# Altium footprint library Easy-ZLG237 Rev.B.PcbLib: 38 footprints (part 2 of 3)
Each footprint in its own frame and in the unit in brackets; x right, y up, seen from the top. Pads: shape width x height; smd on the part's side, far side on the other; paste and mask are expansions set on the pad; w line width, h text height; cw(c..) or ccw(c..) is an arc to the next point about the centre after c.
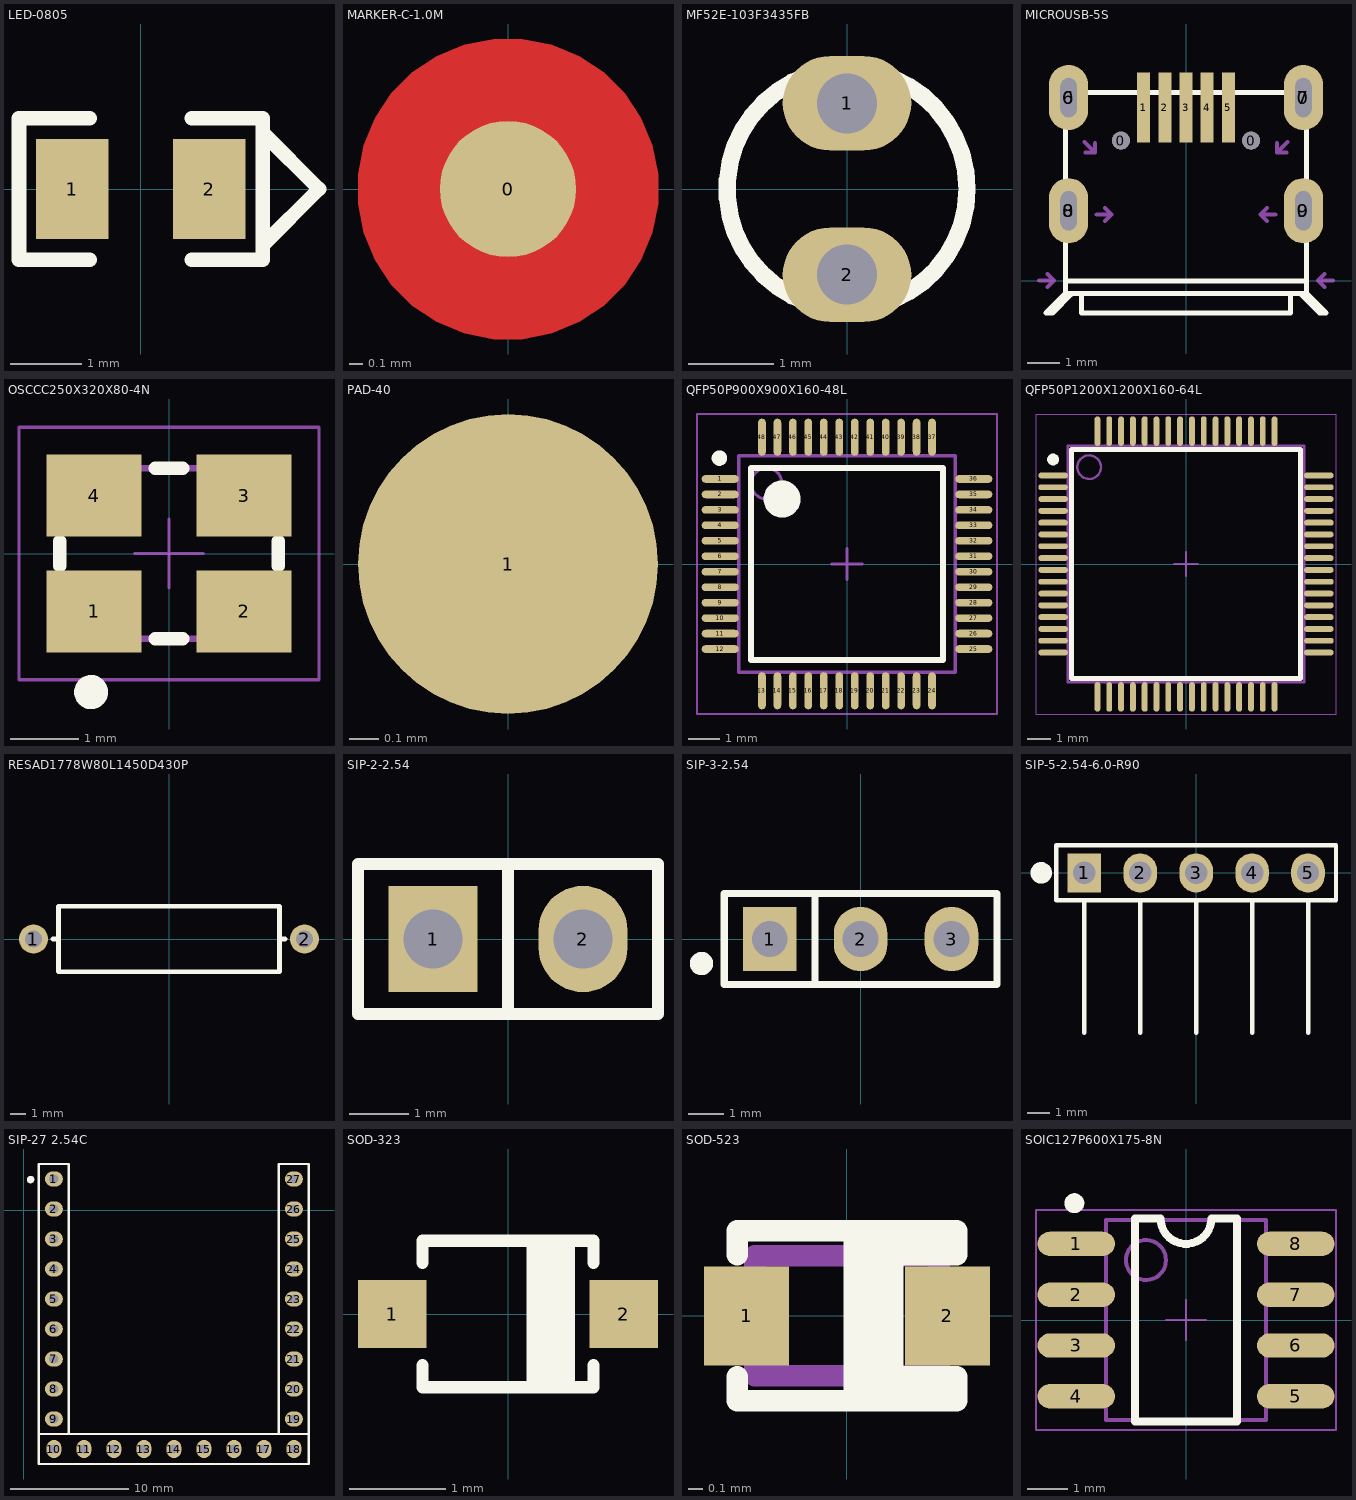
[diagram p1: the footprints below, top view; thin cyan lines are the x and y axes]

## LED-0805 [mm] "170907内距改0.9mm"
pads (2):
  rect 1.014x1.4 smd: 1(-0.957,0) 2(0.957,0)
Top Overlay:
  lines w0.203: -0.711,-0.991 -1.702,-0.991 -1.702,0.991 -0.711,0.991 ; 0.711,-0.991 1.702,-0.991 1.702,0.991 0.711,0.991 ; 1.702,-0.787 2.489,0 1.702,0.787
3D body: height 0.64, standoff 0, extent -1,-0.635 1,0.635
3D body: height 1.1, standoff 0, extent -0.508,-0.508 0.508,0.508

## MARKER-C-1.0M [mm]
height 18.4
pads (1):
  round 1 smd paste-1.016 mask+0.5: 0(0,0)
Top Layer:
  pour cut-out: -1.1,0 -1.1,-0.108 -1.058,-0.321 -0.975,-0.521 -0.854,-0.701 -0.701,-0.854 -0.521,-0.975 -0.321,-1.058 -0.108,-1.1 0,-1.1 0.108,-1.1 0.321,-1.058 0.521,-0.975 0.701,-0.854 0.854,-0.701 0.975,-0.521 1.058,-0.321 1.1,-0.108 1.1,0 1.1,0.108 1.058,0.321 0.975,0.521 0.854,0.701 0.701,0.854 0.521,0.975 0.321,1.058 0.108,1.1 0,1.1 -0.108,1.1 -0.321,1.058 -0.521,0.975 -0.701,0.854 -0.854,0.701 -0.975,0.521 -1.058,0.321 -1.1,0.108

## MF52E-103F3435FB [mm]
pads (2):
  oval 1.5x1.1 hole 0.7: 1(0,1) 2(0,-1)
Top Overlay:
  circle w0.2: c0,0 r1.4

## MICROUSB-5S [mm]
height 0.2
pads (15):
  oval 1.2x2 on Top Paste: 0(-3.6,2.15) 0(-3.6,5.62) 0(3.6,2.15) 0(3.6,5.62)
  round 0.54 hole 0.55 unplated: 0(-2,4.3) 0(2,4.3)
  rect 0.4x2.15 smd: 1(-1.3,5.31) 2(-0.65,5.31) 3(0,5.31) 4(0.65,5.31) 5(1.3,5.31)
  oval 1.2x2 hole 0.5 slot 1.2 at 90 deg: 6(-3.6,5.62) 7(3.6,5.62) 8(-3.6,2.15) 9(3.6,2.15)
Top Overlay:
  lines w0.152: -3.7,0 3.7,0 ; -3.7,0.012 -3.7,5.77 3.7,5.77 3.7,0.012 ; -3.7,0.062 -3.7,-0.388 ; -3.5,-0.398 -4.09,-0.988 -4.3,-0.988 -3.7,-0.388 ; -3.2,-0.388 -3.2,-0.988 3.2,-0.988 3.2,-0.388 ; 3.5,-0.388 4.1,-0.988 4.3,-0.988 3.7,-0.388 ; 3.7,0.062 3.7,-0.388 ; -3.7,-0.388 3.7,-0.388
Mechanical 15:
  lines w0.127: -4.5,0.012 -4.05,0.012 ; -4.25,-0.188 -4.05,0.012 ; -4.25,0.212 -4.05,0.012 ; -3.112,4.255 -2.794,3.937 ; -3.077,3.937 -2.794,3.937 ; -2.794,4.22 -2.794,3.937 ; -2.736,2.032 -2.286,2.032 ; -2.486,1.832 -2.286,2.032 ; -2.486,2.232 -2.286,2.032 ; 2.486,1.832 2.286,2.032 ; 2.486,2.232 2.286,2.032 ; 2.736,2.032 2.286,2.032 ; 2.794,4.22 2.794,3.937 ; 3.077,3.937 2.794,3.937 ; 3.112,4.255 2.794,3.937 ; 4.25,-0.188 4.05,0.012 ; 4.25,0.212 4.05,0.012 ; 4.5,0.012 4.05,0.012
  text "PCB EDGE" at -3,0.212 h0.91
  text "TopPaste" at -2.794,2.667 h0.91

## OSCCC250X320X80-4N [mm]
height 0.8
pads (4):
  rect 1.4x1.2 smd: 1(-1.1,-0.85) 2(1.1,-0.85) 3(1.1,0.85) 4(-1.1,0.85)
Top Overlay:
  circle w0.25: c-1.143,-2.032 r0.125
  lines w0.2: -1.6,-0.178 -1.6,0.178 ; -0.203,-1.25 0.203,-1.25 ; -0.203,1.25 0.203,1.25 ; 1.6,-0.178 1.6,0.178
Mechanical 13:
  lines w0.1: -1.6,-1.15 -1.5,-1.25 ; -1.6,-1.05 -1.4,-1.25 ; -1.6,-0.95 -1.3,-1.25 ; -1.6,-0.85 -1.2,-1.25 ; -1.6,-0.75 -1.1,-1.25 ; -1.6,-0.65 -1,-1.25 ; -1.6,-0.55 -0.9,-1.25 ; -1.6,-0.45 -0.8,-1.25 ; -1.6,-0.35 -0.7,-1.25 ; -1.6,-0.25 -0.6,-1.25 ; -1.6,-1.25 -1.6,1.25 1.6,1.25 1.6,-1.25 -1.6,-1.25
Mechanical 15:
  lines w0.05: -0.5,0 0.5,0 ; 0,-0.5 0,0.5 ; -2.2,-1.85 -2.2,1.85 2.2,1.85 2.2,-1.85 -2.2,-1.85

## PAD-40 [mil]
pads (1):
  round 40 smd paste-43.31: 1(0,0)

## QFP50P900X900X160-48L [mm] "QFP, 48-Leads, Body 7.00x7.00mm, Pitch 0.50mm, IPC High Density"
height 1.6
pads (48):
  oval 1.2x0.25 smd mask+0.051: 1(-4.1,2.75) 2(-4.1,2.25) 3(-4.1,1.75) 4(-4.1,1.25) 5(-4.1,0.75) 6(-4.1,0.25) 7(-4.1,-0.25) 8(-4.1,-0.75) 9(-4.1,-1.25) 10(-4.1,-1.75) 11(-4.1,-2.25) 12(-4.1,-2.75) 25(4.1,-2.75) 26(4.1,-2.25) 27(4.1,-1.75) 28(4.1,-1.25) 29(4.1,-0.75) 30(4.1,-0.25) 31(4.1,0.25) 32(4.1,0.75) 33(4.1,1.25) 34(4.1,1.75) 35(4.1,2.25) 36(4.1,2.75)
  oval 0.25x1.2 smd mask+0.051: 13(-2.75,-4.1) 14(-2.25,-4.1) 15(-1.75,-4.1) 16(-1.25,-4.1) 17(-0.75,-4.1) 18(-0.25,-4.1) 19(0.25,-4.1) 20(0.75,-4.1) 21(1.25,-4.1) 22(1.75,-4.1) 23(2.25,-4.1) 24(2.75,-4.1) 37(2.75,4.1) 38(2.25,4.1) 39(1.75,4.1) 40(1.25,4.1) 41(0.75,4.1) 42(0.25,4.1) 43(-0.25,4.1) 44(-0.75,4.1) 45(-1.25,4.1) 46(-1.75,4.1) 47(-2.25,4.1) 48(-2.75,4.1)
Top Overlay:
  circle w0.6: c-2.1,2.1 r0.3
  circle w0.25: c-4.125,3.425 r0.125
  lines w0.2: -3.1,-3.1 3.1,-3.1 3.1,3.1 -3.1,3.1 -3.1,-3.1
Mechanical 13:
  circle w0.1: c-2.6,2.6 r0.5
  lines w0.1: -3.5,-3.5 3.5,-3.5 3.5,3.5 -3.5,3.5 -3.5,-3.5
Mechanical 15:
  lines w0.05: -4.85,-4.85 4.85,-4.85 4.85,4.85 -4.85,4.85 -4.85,-4.85
  lines w0.1: -0.5,0 0.5,0 ; 0,-0.5 0,0.5
3D body: height 1.6, standoff 0.05, extent -3.5,-3.5 3.5,3.5

## QFP50P1200X1200X160-64L [mm] "QFP, 64-Leads, Body 10.00x10.00mm, Pitch 0.50mm, IPC High Density"
height 1.6
pads (64):
  oval 1.25x0.25 smd mask+0.051: 1(-5.625,3.75) 2(-5.625,3.25) 3(-5.625,2.75) 4(-5.625,2.25) 5(-5.625,1.75) 6(-5.625,1.25) 7(-5.625,0.75) 8(-5.625,0.25) 9(-5.625,-0.25) 10(-5.625,-0.75) 11(-5.625,-1.25) 12(-5.625,-1.75) 13(-5.625,-2.25) 14(-5.625,-2.75) 15(-5.625,-3.25) 16(-5.625,-3.75) 33(5.625,-3.75) 34(5.625,-3.25) 35(5.625,-2.75) 36(5.625,-2.25) 37(5.625,-1.75) 38(5.625,-1.25) 39(5.625,-0.75) 40(5.625,-0.25) 41(5.625,0.25) 42(5.625,0.75) 43(5.625,1.25) 44(5.625,1.75) 45(5.625,2.25) 46(5.625,2.75) 47(5.625,3.25) 48(5.625,3.75)
  oval 0.25x1.25 smd mask+0.051: 17(-3.75,-5.625) 18(-3.25,-5.625) 19(-2.75,-5.625) 20(-2.25,-5.625) 21(-1.75,-5.625) 22(-1.25,-5.625) 23(-0.75,-5.625) 24(-0.25,-5.625) 25(0.25,-5.625) 26(0.75,-5.625) 27(1.25,-5.625) 28(1.75,-5.625) 29(2.25,-5.625) 30(2.75,-5.625) 31(3.25,-5.625) 32(3.75,-5.625) 49(3.75,5.625) 50(3.25,5.625) 51(2.75,5.625) 52(2.25,5.625) 53(1.75,5.625) 54(1.25,5.625) 55(0.75,5.625) 56(0.25,5.625) 57(-0.25,5.625) 58(-0.75,5.625) 59(-1.25,5.625) 60(-1.75,5.625) 61(-2.25,5.625) 62(-2.75,5.625) 63(-3.25,5.625) 64(-3.75,5.625)
Top Overlay:
  circle w0.25: c-5.625,4.425 r0.125
  lines w0.2: -4.85,-4.85 4.85,-4.85 4.85,4.85 -4.85,4.85 -4.85,-4.85
Mechanical 13:
  circle w0.1: c-4.1,4.1 r0.5
  lines w0.1: -5,-5 5,-5 5,5 -5,5 -5,-5
Mechanical 15:
  lines w0.05: -6.35,-6.35 6.35,-6.35 6.35,6.35 -6.35,6.35 -6.35,-6.35
  lines w0.1: -0.5,0 0.5,0 ; 0,-0.5 0,0.5
3D body: height 1.6, standoff 0.05, extent -5,-5 5,5

## RESAD1778W80L1450D430P [mm]
height 1.905
pads (2):
  round 1.9 hole 1.1: 1(-8.89,0) 2(8.89,0)
Top Overlay:
  lines w0.305: -7.62,0 -7.239,0 ; 7.239,0 7.62,0 ; -7.25,-2.15 -7.25,2.15 7.25,2.15 7.25,-2.15 -7.25,-2.15

## SIP-2-2.54 [mm]
pads (2):
  rect 1.5x1.8 hole 1: 1(-1.27,0)
  oval 1.5x1.8 hole 1: 2(1.27,0)
Top Overlay:
  lines w0.2: 0,-1.27 0,1.27 ; -2.54,-1.27 -2.54,1.27 2.54,1.27 2.54,-1.27 -2.54,-1.27
3D body "HEADER.STEP": height 7.58, standoff -2.94, extent -2.54,-1.27 0,1.27
3D body "HEADER.STEP": height 7.58, standoff -2.94, extent 0,-1.27 2.54,1.27

## SIP-3-2.54 [mm]
pads (3):
  rect 1.5x1.8 hole 1: 1(-2.54,0)
  oval 1.5x1.8 hole 1: 2(0,0) 3(2.54,0)
Top Overlay:
  circle w0.4: c-4.445,-0.686 r0.125
  lines w0.2: -1.27,-1.27 -1.27,1.27 ; -3.81,-1.27 -3.81,1.27 3.81,1.27 3.81,-1.27 -3.81,-1.27
3D body "HEADER.STEP": height 7.58, standoff -2.94, extent -3.81,-1.27 -1.27,1.27
3D body "HEADER.STEP": height 7.58, standoff -2.94, extent -1.27,-1.27 1.27,1.27
3D body "HEADER.STEP": height 7.58, standoff -2.94, extent 1.27,-1.27 3.81,1.27

## SIP-5-2.54-6.0-R90 [mil] "引脚伸出部分为6.0mm"
pads (5):
  rect 60x70 hole 40: 1(-200,0)
  oval 60x70 hole 40: 2(-100,0) 3(0,0) 4(100,0) 5(200,0)
Top Overlay:
  circle w20: c-277,0.22 r9.22
  lines w8: -200,-285.43 -200,-49.21 ; -100,-285.43 -100,-49.21 ; 0,-285.43 0,-49.21 ; 100,-285.43 100,-49.21 ; 200,-285.43 200,-49.21 ; -250,-49.21 250,-49.21 250,49.21 -250,49.21 -250,-49.21

## SIP-27 2.54C [mil]
pads (27):
  oval 60x50 hole 31.5: 1(100,105) 2(100,5) 3(100,-95) 4(100,-195) 5(100,-295) 6(100,-395) 7(100,-495) 8(100,-595) 9(100,-695) 19(900,-695) 20(900,-595) 21(900,-495) 22(900,-395) 23(900,-295) 24(900,-195) 25(900,-95) 26(900,5) 27(900,105)
  oval 50x60 hole 31.5: 10(100,-795) 11(200,-795) 12(300,-795) 13(400,-795) 14(500,-795) 15(600,-795) 16(700,-795) 17(800,-795) 18(900,-795)
Top Overlay:
  circle w15: c22.01,103 r5
  lines w8: 945,-845 50,-845 50,-745 ; 945,-745 50,-745 ; 950,-845 950,-745 ; 50,-745 50,155 150,155 150,-745 50,-745 ; 950,-745 850,-745 850,155 950,155 950,-745

## SOD-323 [mil]
height 38
pads (2):
  rect 28x28 smd: 1(-47.5,0) 2(47.5,0)
Top Overlay:
  lines w5: -35,-21 -35,-30 35,-30 35,-21 ; -35,21 -35,30 35,30 35,21 ; 10,-30 10,30 ; 15,-30 15,30 ; 20,-30 20,30 ; 25,-30 25,30
3D body "SOD-323.STEP": height 39.37, standoff 0, extent -51,-26 51.36,25.18

## SOD-523 [mm] "依手册推荐封装制作，未验证"
height 0.635
pads (2):
  rect 0.6x0.7 smd: 1(-0.71,0) 2(0.71,0)
Top Overlay:
  rectangle: -0.025,-0.609 0.4,0.635
  rectangle: 0.254,-0.6 0.777,-0.356
  rectangle: 0.254,0.356 0.777,0.6
  lines w0.152: -0.777,-0.432 -0.777,-0.6 0.777,-0.6 0.777,-0.432 ; -0.777,0.432 -0.777,0.6 0.777,0.6 0.777,0.432
Mechanical 15:
  lines w0.152: -0.65,-0.425 0.65,-0.425 0.65,0.425 0,0.425 -0.65,0.425 -0.65,-0.425

## SOIC127P600X175-8N [mil]
pads (8):
  oval 76.06x24 smd: 1(-108.03,75) 2(-108.03,25) 3(-108.03,-25) 4(-108.03,-75) 5(108.03,-75) 6(108.03,-25) 7(108.03,25) 8(108.03,75)
Top Overlay:
  circle w9.84: c-109.92,115 r4.92
  lines w7.87: -50,-100 50,-100 50,100 25,100 cw(c0,100) -25,100 -50,100 -50,-100
Mechanical 15:
  circle w3.94: c-39.37,59.06 r19.68
  lines w3.94: -78.74,-98.43 -78.74,98.43 78.74,98.43 78.74,-98.43 -78.74,-98.43
  text "1" at 17.71,-6.47 h29.53
Mechanical 16:
  lines w0.04: -78.74,-98.43 -78.74,98.43 78.74,98.43 78.74,-98.43 -78.74,-98.43
  lines w1.97: -19.68,0 19.68,0 ; 0,-19.68 0,19.68 ; -147.64,-108.27 -147.64,108.27 147.64,108.27 147.64,-108.27 -147.64,-108.27
3D body "SW3DPS-SO-8 (PIC12FXXX)-DEFAULT.STEP": height 61.02, standoff -1.97, extent -117.91,-96 117.91,96.91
